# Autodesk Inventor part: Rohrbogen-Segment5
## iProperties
Created: 2006-10
Part Number: Rohrbogen-Segment5
Cost Center: 6,92 kg
Material: 1.4301 (X5CrNi18 10)
Document SubType Name: Sheet Metal
Designer: grote
Authority: 865130 mm^3
Manufacturer: Standard
Standards Organization: Custom
Objekthöhe: 10,000 mm
SaveDate: 2006-10-11
SaveTime: 08:22
FileName: Rohrbogen-Segment5
TotalMass: 6,92 kg
TotalVolume: 865130 mm^3
SM_Thickness: 10 mm
SM_Style: NIRO-V80(t =4-10 mm)
SM_Extents: 424,771 mm x 469,136 mm
SM_Square: 199275 mm²
SM_Extents_Width: 424,771 mm
SM_Extents_Length: 469,136 mm
Author: grote
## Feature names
1. Trennen1
2. Trennen2
3. Abgeleiteter Körper1 [Tagging]
4. ExtrusionAbwicklung1
